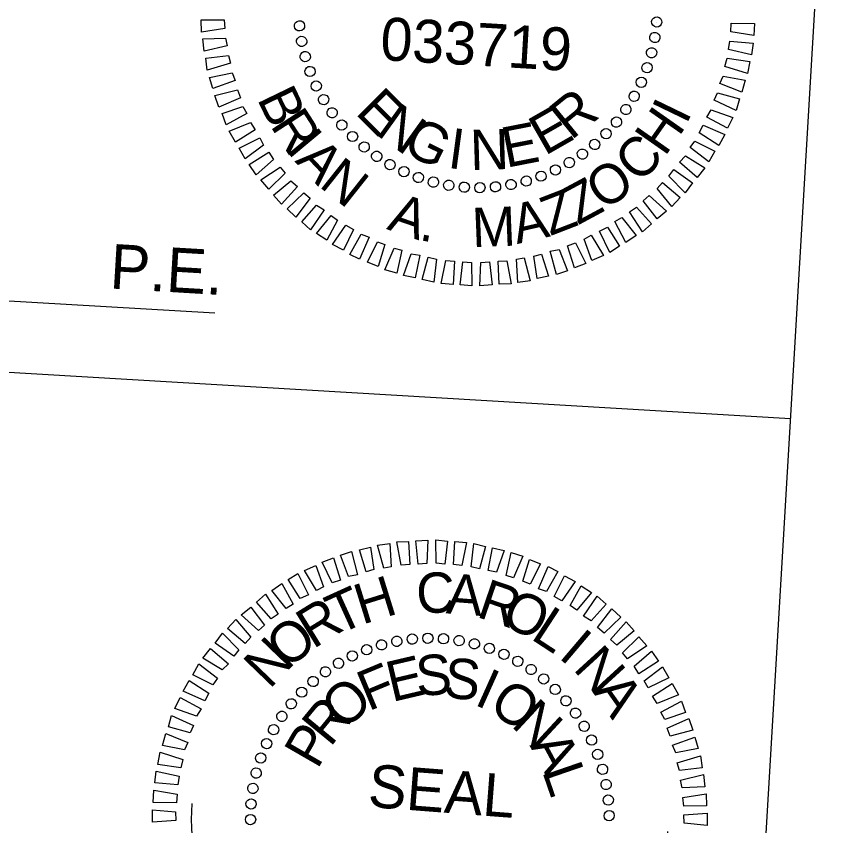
# Model space of a CAD drawing. Extents: x 1998567 to 2027801, y 439108 to 451079.
# Drawn here: x 2017808 to 2018722, y 439966 to 440872 of the extents above; entities that cross this region are included whole.
import ezdxf

# ---------------------------------------------------------------- set-up
doc = ezdxf.new("R2010")
doc.units = 0
for name, color, linetype in [('Scratch_Level_0', 7, 'Continuous'), ('Sheet Professional Seal CELL', 7, 'Continuous'), ('Sheet Profile Grid Minor CELL', 7, 'Continuous'), ('Sheet Title CELL', 7, 'Continuous')]:
    doc.layers.add(name, color=color, linetype=linetype)

msp = doc.modelspace()

# ---------------------------------------------------------------- linework, layer by layer
at = {"layer": 'Scratch_Level_0'}
msp.add_arc((2018271.09, 439975.33), 266.91, 176.62643, 356.62643, dxfattribs=at)
at = {"layer": 'Sheet Professional Seal CELL'}
for p, q in [((2018125.38, 440861.1), (2018125.38, 440861.1)), ((2018525.11, 440865.18), (2018525.11, 440865.18)), ((2018127.54, 440843.34), (2018127.54, 440843.34)), ((2018522.88, 440847.68), (2018522.88, 440847.68)), ((2018131.34, 440826.29), (2018131.34, 440826.29)), ((2018519.07, 440830.68), (2018519.07, 440830.68)), ((2018514.49, 440814.12), (2018514.49, 440814.12)), ((2018136.79, 440809.94), (2018136.79, 440809.94)), ((2018507.91, 440797.68), (2018507.91, 440797.68)), ((2018143.86, 440793.89), (2018143.86, 440793.89)), ((2018152.15, 440778.18), (2018152.15, 440778.18)), ((2018499.78, 440782.13), (2018499.78, 440782.13)), ((2018161.31, 440763.62), (2018161.31, 440763.62)), ((2018490.88, 440767.03), (2018490.88, 440767.03)), ((2018480.05, 440753.24), (2018480.05, 440753.24)), ((2018172.51, 440749.73), (2018172.51, 440749.73)), ((2018184.18, 440737.02), (2018184.18, 440737.02)), ((2018468.44, 440739.9), (2018468.44, 440739.9)), ((2018197.52, 440725.42), (2018197.52, 440725.42)), ((2018455.73, 440728.23), (2018455.73, 440728.23)), ((2018211.31, 440714.59), (2018211.31, 440714.59)), ((2018441.85, 440717.03), (2018441.85, 440717.03)), ((2018226.41, 440705.68), (2018226.41, 440705.68)), ((2018427.29, 440707.87), (2018427.29, 440707.87)), ((2018241.96, 440697.55), (2018241.96, 440697.55)), ((2018411.57, 440699.58), (2018411.57, 440699.58)), ((2018258.4, 440690.98), (2018258.4, 440690.98)), ((2018274.96, 440686.39), (2018274.96, 440686.39)), ((2018379.18, 440687.06), (2018379.18, 440687.06)), ((2018395.53, 440692.51), (2018395.53, 440692.51)), ((2018291.96, 440682.59), (2018291.96, 440682.59)), ((2018309.46, 440680.35), (2018309.46, 440680.35)), ((2018327.06, 440679.72), (2018327.06, 440679.72)), ((2018344.37, 440681.1), (2018344.37, 440681.1)), ((2018362.13, 440683.26), (2018362.13, 440683.26)), ((2018251.6, 440174.82), (2018251.6, 440174.82)), ((2018268.91, 440176.21), (2018268.91, 440176.21)), ((2018286.5, 440175.57), (2018286.5, 440175.57)), ((2018216.78, 440168.86), (2018216.78, 440168.86)), ((2018233.84, 440172.66), (2018233.84, 440172.66)), ((2018304, 440173.34), (2018304, 440173.34)), ((2018321, 440169.53), (2018321, 440169.53)), ((2018184.39, 440156.34), (2018184.39, 440156.34)), ((2018200.44, 440163.41), (2018200.44, 440163.41)), ((2018337.56, 440164.95), (2018337.56, 440164.95)), ((2018354, 440158.37), (2018354, 440158.37)), ((2018168.68, 440148.06), (2018168.68, 440148.06)), ((2018369.55, 440150.24), (2018369.55, 440150.24)), ((2018154.11, 440138.9), (2018154.11, 440138.9)), ((2018384.66, 440141.33), (2018384.66, 440141.33)), ((2018398.44, 440130.5), (2018398.44, 440130.5)), ((2018140.23, 440127.69), (2018140.23, 440127.69)), ((2018127.52, 440116.02), (2018127.52, 440116.02)), ((2018411.78, 440118.9), (2018411.78, 440118.9)), ((2018115.92, 440102.68), (2018115.92, 440102.68)), ((2018423.45, 440106.19), (2018423.45, 440106.19)), ((2018105.09, 440088.89), (2018105.09, 440088.89)), ((2018434.66, 440092.31), (2018434.66, 440092.31)), ((2018443.82, 440077.74), (2018443.82, 440077.74)), ((2018096.18, 440073.79), (2018096.18, 440073.79)), ((2018088.05, 440058.24), (2018088.05, 440058.24)), ((2018452.11, 440062.03), (2018452.11, 440062.03)), ((2018081.47, 440041.8), (2018081.47, 440041.8)), ((2018459.17, 440045.98), (2018459.17, 440045.98)), ((2018464.62, 440029.63), (2018464.62, 440029.63)), ((2018076.89, 440025.24), (2018076.89, 440025.24)), ((2018468.42, 440012.58), (2018468.42, 440012.58)), ((2018073.08, 440008.24), (2018073.08, 440008.24)), ((2018470.58, 439994.82), (2018470.58, 439994.82)), ((2018070.85, 439990.74), (2018070.85, 439990.74)), ((2018271.09, 439975.33), (2018271.09, 439975.33)), ((2018471.97, 439977.51), (2018471.97, 439977.51)), ((2018070.21, 439973.15), (2018070.21, 439973.15))]:
    msp.add_line(p, q, dxfattribs=at)
for points in [[(2018041.85, 440858.01), (2018015.57, 440853.95), (2018015.17, 440867.59), (2018040.82, 440867.69)], [(2018608.38, 440863.88), (2018634.41, 440863.55), (2018633.61, 440849.97), (2018607.82, 440854.3)], [(2018044.32, 440838.63), (2018018.71, 440832.53), (2018017.12, 440846.24), (2018042.42, 440847.16)], [(2018606.8, 440843.94), (2018632.71, 440841.61), (2018631.14, 440828.48), (2018605.44, 440834.4)], [(2018047.98, 440819.18), (2018021.88, 440811.5), (2018020.26, 440824.82), (2018045.68, 440827.73)], [(2018603.68, 440824.89), (2018629.09, 440820.99), (2018626.7, 440807.5), (2018601.12, 440815.42)], [(2018053.24, 440799.64), (2018028.27, 440790.69), (2018024.61, 440803.33), (2018049.74, 440808.26)], [(2018599.28, 440804.71), (2018623.85, 440800.06), (2018620.26, 440786.65), (2018595.59, 440796.52)], [(2018059.32, 440780.45), (2018035.05, 440769.86), (2018030.62, 440782.94), (2018055.84, 440789.47)], [(2018592.96, 440785.85), (2018617.41, 440779.2), (2018613.84, 440766.19), (2018589.27, 440777.66)], [(2018066.29, 440762.8), (2018043.11, 440750.15), (2018038.65, 440762.83), (2018061.95, 440770.67)], [(2018585.84, 440767.04), (2018610.18, 440758.39), (2018604.26, 440746.32), (2018580.96, 440758.91)], [(2018075.64, 440744.62), (2018053.58, 440730.7), (2018046.7, 440743.12), (2018070.52, 440752.94)], [(2018576.82, 440749.94), (2018601.04, 440739.3), (2018594.32, 440727.27), (2018572.31, 440741.39)], [(2018085.06, 440727.64), (2018064.5, 440712.02), (2018057.6, 440724.05), (2018080.71, 440735.51)], [(2018567.75, 440732.04), (2018589.92, 440720.72), (2018583.21, 440708.69), (2018562.51, 440724.74)], [(2018096.12, 440711.36), (2018076.69, 440694.47), (2018068.94, 440705.75), (2018091, 440719.68)], [(2018557.16, 440715.44), (2018578.81, 440702.14), (2018570.17, 440691.43), (2018550.34, 440708.63)], [(2018109.25, 440696.16), (2018090.97, 440678.41), (2018081.95, 440688.55), (2018103.63, 440702.9)], [(2018544.24, 440700.17), (2018565, 440685.32), (2018556.73, 440674.19), (2018538.6, 440692.89)], [(2018122.8, 440681.34), (2018105.2, 440661.54), (2018096.18, 440671.69), (2018115.56, 440687.78)], [(2018531.36, 440685.7), (2018551.21, 440668.91), (2018541.81, 440659.04), (2018525.35, 440678.85)], [(2018137.24, 440668.07), (2018121.17, 440646.97), (2018111.31, 440656.37), (2018129.98, 440674.1)], [(2018516.49, 440671.35), (2018535.89, 440653.78), (2018525.37, 440645.19), (2018509.73, 440665.34)], [(2018152.91, 440655.12), (2018137.57, 440632.79), (2018127.68, 440641.78), (2018144.4, 440660.43)], [(2018502.49, 440658.16), (2018519.03, 440639.55), (2018508.88, 440630.53), (2018494.58, 440653.01)], [(2018167.84, 440643.42), (2018155.72, 440621.3), (2018144.14, 440628.79), (2018160.54, 440648.66)], [(2018485.79, 440646.72), (2018501.83, 440626.54), (2018490.55, 440618.79), (2018477.9, 440641.97)], [(2018185.67, 440633.16), (2018174.3, 440610.18), (2018162.25, 440616.5), (2018177.15, 440638.07)], [(2018469.91, 440635.63), (2018483.48, 440614.4), (2018472.65, 440607.42), (2018460.84, 440631.36)], [(2018203.19, 440624.51), (2018192.53, 440599.89), (2018181.63, 440605.35), (2018194.17, 440627.85)], [(2018451.75, 440626.69), (2018465.25, 440604.25), (2018452.5, 440598.59), (2018443.88, 440622.34)], [(2018220.74, 440616.26), (2018213.29, 440591.86), (2018201.15, 440596.58), (2018212.52, 440619.55)], [(2018434.02, 440618.12), (2018445.48, 440595), (2018432.77, 440590.14), (2018425.02, 440615.04)], [(2018239.6, 440609.94), (2018234.08, 440584.22), (2018220.69, 440588.22), (2018231.33, 440612.43)], [(2018259.7, 440604.35), (2018254.6, 440579.01), (2018241.54, 440581.78), (2018250.19, 440606.11)], [(2018396.01, 440605.53), (2018403.78, 440581.03), (2018391.19, 440578.17), (2018387.46, 440603.23)], [(2018415.95, 440610.77), (2018424.97, 440586.99), (2018412.71, 440582.91), (2018405.83, 440608.96)], [(2018278.68, 440600.02), (2018275.56, 440574.16), (2018262.52, 440577.34), (2018269.19, 440602.19)], [(2018298.58, 440597.65), (2018297.05, 440571.69), (2018283.89, 440572.87), (2018289.02, 440598.61)], [(2018317.72, 440596.12), (2018318.19, 440570.05), (2018305.03, 440571.22), (2018308.16, 440597.08)], [(2018337.8, 440596.94), (2018340.69, 440571.13), (2018327.02, 440570.33), (2018328.15, 440596.31)], [(2018357.11, 440598.21), (2018361.99, 440572.27), (2018348.75, 440571.85), (2018347.46, 440597.57)], [(2018376.54, 440601.47), (2018383.44, 440575.82), (2018369.7, 440573.82), (2018368.03, 440599.97)], [(2018258.16, 440258.98), (2018255.27, 440284.8), (2018268.94, 440285.59), (2018267.81, 440259.61)], [(2018278.24, 440259.8), (2018277.78, 440285.87), (2018290.93, 440284.7), (2018287.8, 440258.84)], [(2018297.39, 440258.27), (2018298.92, 440284.23), (2018312.07, 440283.05), (2018306.95, 440257.31)], [(2018199.95, 440250.39), (2018192.18, 440274.89), (2018204.77, 440277.76), (2018208.5, 440252.69)], [(2018219.43, 440254.45), (2018212.52, 440280.1), (2018226.26, 440282.1), (2018227.93, 440255.96)], [(2018238.85, 440257.72), (2018233.97, 440283.65), (2018247.22, 440284.07), (2018248.51, 440258.35)], [(2018317.28, 440255.9), (2018320.41, 440281.76), (2018333.44, 440278.59), (2018326.77, 440253.74)], [(2018336.26, 440251.57), (2018341.36, 440276.92), (2018354.42, 440274.14), (2018345.77, 440249.81)], [(2018180.01, 440245.16), (2018170.99, 440268.93), (2018183.26, 440273.01), (2018190.13, 440246.96)], [(2018356.36, 440245.98), (2018361.89, 440271.7), (2018375.28, 440267.7), (2018364.63, 440243.49)], [(2018144.21, 440229.24), (2018130.71, 440251.67), (2018143.46, 440257.33), (2018152.08, 440233.58)], [(2018161.95, 440237.81), (2018150.49, 440260.92), (2018163.19, 440265.78), (2018170.94, 440240.88)], [(2018375.23, 440239.66), (2018382.67, 440264.06), (2018394.82, 440259.34), (2018383.45, 440236.37)], [(2018126.05, 440220.29), (2018112.48, 440241.52), (2018123.31, 440248.5), (2018135.12, 440224.56)], [(2018392.77, 440231.41), (2018403.44, 440256.03), (2018414.34, 440250.58), (2018401.79, 440228.08)], [(2018410.29, 440222.77), (2018421.66, 440245.74), (2018433.71, 440239.42), (2018418.82, 440217.86)], [(2018110.17, 440209.2), (2018094.13, 440229.38), (2018105.41, 440237.13), (2018118.07, 440213.95)], [(2018428.12, 440212.5), (2018440.24, 440234.62), (2018451.82, 440227.13), (2018435.42, 440207.26)], [(2018093.47, 440197.77), (2018076.94, 440216.37), (2018087.09, 440225.39), (2018101.39, 440202.91)], [(2018443.06, 440200.8), (2018458.4, 440223.14), (2018468.28, 440214.14), (2018451.56, 440195.49)], [(2018079.47, 440184.57), (2018060.07, 440202.14), (2018070.6, 440210.74), (2018086.24, 440190.58)], [(2018458.72, 440187.86), (2018474.79, 440208.95), (2018484.65, 440199.55), (2018465.98, 440181.82)], [(2018064.6, 440170.22), (2018044.75, 440187.01), (2018054.15, 440196.88), (2018070.61, 440177.08)], [(2018473.17, 440174.58), (2018490.76, 440194.38), (2018499.78, 440184.23), (2018480.4, 440168.15)], [(2018051.73, 440155.75), (2018030.96, 440170.6), (2018039.23, 440181.73), (2018057.37, 440163.03)], [(2018486.72, 440159.76), (2018504.99, 440177.52), (2018514.01, 440167.37), (2018492.33, 440153.02)], [(2018038.81, 440140.48), (2018017.15, 440153.78), (2018025.8, 440164.49), (2018045.62, 440147.3)], [(2018499.84, 440144.56), (2018519.27, 440161.45), (2018527.02, 440150.17), (2018504.96, 440136.25)], [(2018028.21, 440123.88), (2018006.04, 440135.2), (2018012.76, 440147.23), (2018033.45, 440131.18)], [(2018510.91, 440128.28), (2018531.46, 440143.9), (2018538.37, 440131.87), (2018515.25, 440120.41)], [(2018019.14, 440105.98), (2017994.93, 440116.63), (2018001.65, 440128.65), (2018023.65, 440114.53)], [(2018520.32, 440111.3), (2018542.38, 440125.22), (2018549.26, 440112.8), (2018525.44, 440102.98)], [(2018010.12, 440088.88), (2017985.79, 440097.53), (2017991.71, 440109.6), (2018015.01, 440097.01)], [(2018529.67, 440093.12), (2018552.85, 440105.77), (2018557.32, 440093.09), (2018534.01, 440085.25)], [(2018003, 440070.07), (2017978.55, 440076.72), (2017982.12, 440089.73), (2018006.69, 440078.27)], [(2018536.64, 440075.48), (2018560.91, 440086.07), (2018565.35, 440072.98), (2018540.12, 440066.46)], [(2017996.68, 440051.21), (2017972.11, 440055.86), (2017975.71, 440069.27), (2018000.37, 440059.41)], [(2018542.72, 440056.28), (2018567.69, 440065.23), (2018571.36, 440052.59), (2018546.22, 440047.66)], [(2017992.28, 440031.03), (2017966.87, 440034.93), (2017969.27, 440048.42), (2017994.85, 440040.5)], [(2018547.98, 440036.74), (2018574.08, 440044.42), (2018575.7, 440031.1), (2018550.28, 440028.19)], [(2017989.16, 440011.98), (2017963.25, 440014.31), (2017964.83, 440027.44), (2017990.52, 440021.52)], [(2018551.65, 440017.29), (2018577.25, 440023.4), (2018578.84, 440009.68), (2018553.55, 440008.77)], [(2017987.58, 439992.04), (2017961.56, 439992.37), (2017962.36, 440005.95), (2017988.15, 440001.62)], [(2018554.11, 439997.91), (2018580.39, 440001.97), (2018580.79, 439988.33), (2018555.14, 439988.24)], [(2017986.8, 439972.05), (2017960.66, 439970.39), (2017960.66, 439984.01), (2017986.57, 439981.68)], [(2018555.38, 439978.61), (2018581.52, 439980.27), (2018581.52, 439966.65), (2018555.61, 439968.98)]]:
    msp.add_lwpolyline(points, close=True, dxfattribs=at)
for centre, major_axis in [((2018524.93, 440865.29), (5.74, -0.44)), ((2018125.2, 440860.92), (-5.73, -0.56)), ((2018522.83, 440847.91), (5.68, -0.94)), ((2018127.67, 440843.59), (-5.66, -1.06)), ((2018131.65, 440826.55), (-5.55, -1.55)), ((2018519.23, 440830.79), (5.58, -1.43)), ((2018137.09, 440809.91), (-5.39, -2.03)), ((2018514.15, 440814.04), (5.43, -1.91)), ((2018143.97, 440793.82), (-5.19, -2.49)), ((2018507.63, 440797.79), (5.25, -2.38)), ((2018499.72, 440782.18), (5.02, -2.83)), ((2018152.22, 440778.38), (-4.96, -2.93)), ((2018161.79, 440763.72), (-4.68, -3.36)), ((2018490.48, 440767.31), (4.75, -3.25)), ((2018479.97, 440753.31), (4.45, -3.65)), ((2018172.59, 440749.95), (-4.37, -3.75)), ((2018184.56, 440737.18), (-4.03, -4.12)), ((2018468.29, 440740.28), (4.12, -4.03)), ((2018197.59, 440725.49), (-3.65, -4.45)), ((2018455.51, 440728.31), (3.75, -4.37)), ((2018441.75, 440717.51), (3.36, -4.68)), ((2018211.59, 440714.99), (-3.25, -4.75)), ((2018427.09, 440707.94), (2.93, -4.96)), ((2018226.46, 440705.75), (-2.83, -5.02)), ((2018242.07, 440697.83), (-2.38, -5.25)), ((2018411.65, 440699.69), (2.49, -5.19)), ((2018258.32, 440691.31), (-1.91, -5.43)), ((2018395.55, 440692.81), (2.03, -5.39)), ((2018275.07, 440686.23), (-1.43, -5.58)), ((2018292.19, 440682.63), (-0.94, -5.68)), ((2018309.57, 440680.54), (-0.44, -5.74)), ((2018344.54, 440680.92), (0.56, -5.73)), ((2018361.87, 440683.39), (1.06, -5.66)), ((2018378.92, 440687.37), (1.55, -5.55)), ((2018327.07, 440679.96), (0.06, -5.76)), ((2018217.04, 440168.55), (-1.55, 5.55)), ((2018234.09, 440172.53), (-1.06, 5.66)), ((2018251.42, 440175), (-0.56, 5.73)), ((2018268.9, 440175.96), (-0.06, 5.76)), ((2018286.39, 440175.38), (0.44, 5.74)), ((2018303.77, 440173.29), (0.94, 5.68)), ((2018320.9, 440169.69), (1.43, 5.58)), ((2018200.41, 440163.11), (-2.03, 5.39)), ((2018337.65, 440164.61), (1.91, 5.43)), ((2018184.31, 440156.23), (-2.49, 5.19)), ((2018353.89, 440158.09), (2.38, 5.25)), ((2018369.5, 440150.17), (2.83, 5.02)), ((2018168.88, 440147.98), (-2.93, 4.96)), ((2018384.37, 440140.93), (3.25, 4.75)), ((2018154.22, 440138.42), (-3.36, 4.68)), ((2018140.45, 440127.61), (-3.75, 4.37)), ((2018398.37, 440130.43), (3.65, 4.45)), ((2018127.67, 440115.64), (-4.12, 4.03)), ((2018411.4, 440118.75), (4.03, 4.12)), ((2018423.37, 440105.97), (4.37, 3.75)), ((2018115.99, 440102.61), (-4.45, 3.65)), ((2018105.49, 440088.61), (-4.75, 3.25)), ((2018434.18, 440092.2), (4.68, 3.36)), ((2018443.74, 440077.54), (4.96, 2.93)), ((2018096.24, 440073.74), (-5.02, 2.83)), ((2018451.99, 440062.11), (5.19, 2.49)), ((2018088.33, 440058.13), (-5.25, 2.38)), ((2018081.81, 440041.89), (-5.43, 1.91)), ((2018458.87, 440046.01), (5.39, 2.03)), ((2018076.73, 440025.14), (-5.58, 1.43)), ((2018464.31, 440029.37), (5.55, 1.55)), ((2018073.13, 440008.01), (-5.68, 0.94)), ((2018468.29, 440012.33), (5.66, 1.06)), ((2018470.76, 439995), (5.73, 0.56)), ((2018071.03, 439990.63), (-5.74, 0.44)), ((2018471.72, 439977.52), (5.76, 0.06)), ((2018070.46, 439973.14), (-5.76, -0.06))]:
    msp.add_ellipse(centre, major_axis=major_axis, ratio=0.999708, dxfattribs=at)
at = {"layer": 'Sheet Title CELL'}
for p, q in [((2018627.68, 439622.97), (2018721.83, 441220.19)), ((2016590.33, 440624.69), (2018030.34, 440539.8)), ((2016480.87, 440551.15), (2018674.76, 440421.82))]:
    msp.add_line(p, q, dxfattribs=at)

# ---------------------------------------------------------------- texts
at = {"layer": 'Sheet Professional Seal CELL'}
for s, height, rotation, p in [('E', 45.1, 314.90331, (2018186.53, 440763.33)), ('R', 45.11, 39.10783, (2018429.12, 440732.2)), ('N', 45.11, 324.26038, (2018209.22, 440740.36)), ('E', 45.11, 29.75051, (2018399.66, 440715.1)), ('G', 45.11, 333.61666, (2018238.51, 440720.6)), ('E', 45.11, 11.03819, (2018356.42, 440702.03)), ('I', 45.1, 352.32763, (2018289.92, 440702.34)), ('N', 45.1, 1.68281, (2018316.61, 440699.57)), ('C', 45.1, 2.8463, (2018256.88, 440203.36)), ('H', 45.11, 17.2459, (2018195.25, 440190.97)), ('A', 45.1, 355.64675, (2018288.57, 440203.9)), ('R', 45.11, 341.24752, (2018322.02, 440200.32)), ('T', 45.11, 24.4462, (2018168.52, 440179.32)), ('O', 45.1, 334.04759, (2018348.42, 440192.76)), ('R', 45.11, 31.64693, (2018140.33, 440163.35)), ('L', 45.11, 326.8473, (2018382.69, 440175.91)), ('O', 45.11, 38.84817, (2018111.32, 440140.22)), ('I', 45.1, 319.64657, (2018413.9, 440154.84)), ('N', 45.11, 46.04993, (2018091.58, 440118.14)), ('N', 45.11, 312.44533, (2018430.34, 440141.45)), ('E', 45.11, 13.23749, (2018228.61, 440104.45)), ('S', 45.1, 3.88203, (2018256.66, 440111.21)), ('F', 45.1, 22.59346, (2018202.35, 440093.98)), ('S', 45.1, 354.52683, (2018285.43, 440109.92)), ('I', 45.11, 335.81603, (2018319.45, 440102.3)), ('O', 45.11, 41.30766, (2018174.61, 440071.97)), ('O', 45.11, 326.45991, (2018335.09, 440095.77)), ('A', 45.11, 305.24358, (2018452.51, 440116.5)), ('R', 45.11, 50.66608, (2018159.48, 440053.23)), ('N', 45.11, 317.10304, (2018360.9, 440078.22)), ('P', 45.12, 60.02531, (2018145.2, 440028.43)), ('A', 45.11, 298.38669, (2018382.44, 440056.12)), ('L', 45.12, 289.02728, (2018396.39, 440027.65)), ('SEAL', 47.986, 355.62643, (2018200.88, 439987.48))]:
    msp.add_text(s, height=height, rotation=rotation, dxfattribs=at).set_placement(p)
at = {"layer": 'Sheet Profile Grid Minor CELL'}
for s, height, rotation, p in [('033719', 47.986, 356.62643, (2018214.75, 440822.91)), ('B', 44, 295.77934, (2018077.31, 440779.46)), ('I', 44, 64.21906, (2018558, 440749.56)), ('R', 44, 302.90613, (2018091.77, 440749.53)), ('H', 44, 54.97426, (2018533.92, 440713.81)), ('I', 44, 309.83258, (2018109.27, 440722.37)), ('C', 44, 46.10155, (2018505.69, 440683.56)), ('A', 44, 313.35304, (2018119.4, 440709.43)), ('N', 44, 321.53884, (2018145.86, 440681.92)), ('O', 44, 35.39705, (2018465.95, 440653.4)), ('Z', 44, 28.27025, (2018436.67, 440637.66)), ('Z', 44, 21.14346, (2018405.67, 440625.66)), ('A', 44, 340.9157, (2018221.92, 440633.78)), ('M', 44, 2.28178, (2018318.91, 440613.23)), ('A', 44, 12.95766, (2018368.55, 440616.76)), ('.', 44, 349.1015, (2018258.11, 440621.63))]:
    msp.add_text(s, height=height, rotation=rotation, dxfattribs=at).set_placement(p)
at = {"layer": 'Sheet Title CELL'}
msp.add_text('P.E.', height=49.995, rotation=356.62643, dxfattribs=at).set_placement((2017912.15, 440567.25))

doc.saveas('drawing.dxf')
